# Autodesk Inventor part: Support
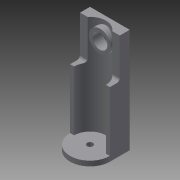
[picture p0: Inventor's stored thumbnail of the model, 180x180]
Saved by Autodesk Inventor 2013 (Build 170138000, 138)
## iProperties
Created: 2006-03
Part Number: Support
Document SubType Name: Modeling
Designer: debonom
Manufacturer: Standard
Standards Organization: Custom
Mass: 42.849 g
Surface Area: 163.994 cm^2
Volume: 42.849 cm^3
Density: 1 g/cm^3
Material: Generic
Author: debonom
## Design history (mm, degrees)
sketch "Sketch4"
  geometry: L1 (0, -28)-(0, 28) reference; L2 (-28, 0)-(28, 0) reference; L3 (20, 0)-(20, -20); L4 (20, -20)-(-20, -20); L5 (-20, -20)-(-20, 0); C1 r 3 at (0, 0); A1 r 20 centre (0, 0) between (20, 0) and (-20, 0); 1 further point
  constraints: 6 end point, 2 centre point, 2 coincident, 2 perpendicular, 2 point on circle, 2 tangent, 1 parallel, 1 point on line
  dimensions: "d7" = 20 radius of A1; "d8" = 20 distance of L3.start L3.end; "d9" = 6 diameter of C1
extrude "Extrusion3" new body sketch "Sketch4" distance "d10" = 5; taper "d11" = 0 deg
sketch "Sketch5"
  geometry: L1 (0, 28)-(0, -28) reference; L2 (28, 0)-(-28, 0) reference; L3 (-16, 0)-(-20, 0); L4 (-20, 0)-(-20, 20); L5 (-20, 20)-(20, 20); L6 (20, 20)-(20, 0); A1 r 16 centre (0, 0) between (16, 0) and (-16, 0); 1 further point
  constraints: 8 end point, 2 perpendicular, 2 point on circle, 2 point on line, 1 centre point, 1 coincident, 1 collinear, 1 parallel
  dimensions: "d14" = 16 radius of A1
extrude "Extrusion4" join sketch "Sketch5" distance "d12" = 100; taper "d13" = 0 deg
feature "Sculpt1"
  workplane "Work Plane1"
  workplane "Work Plane2"
sketch "Sketch6"
  geometry: L1 (-12.49, 21)-(-12.49, -126) reference; L2 (0, 0)-(-24.98, 0) reference; C1 r 11 at (-12.49, -15); 1 further point
  constraints: 1 centre point, 1 point on line
  dimensions: "d17" = 15 distance from line of L2 C1.centre; "d18" = 22 diameter of C1
extrude "Extrusion5" join sketch "Sketch6" stored distance "d19" = 50; taper "d20" = 0 deg
sketch "Sketch7"
  geometry: C1 r 11 at (0, 0) reference; C2 r 7.5 at (0, 0); 1 further point
  constraints: 1 centre point, 1 coincident
  dimensions: "d21" = 15 diameter of C2
extrude "Extrusion6" cut sketch "Sketch7" distance "d22" = 50; taper "d23" = 0 deg
fillet "Fillet1" dims "d24" = 3
body "Solid1"
